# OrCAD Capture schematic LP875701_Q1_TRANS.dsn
size Custom; title: LP875701-Q1 4-Phase 10A Buck Converter with Integrated Switches; rev: 1.0; note: SNVSxxxx –DECEMBER 2018
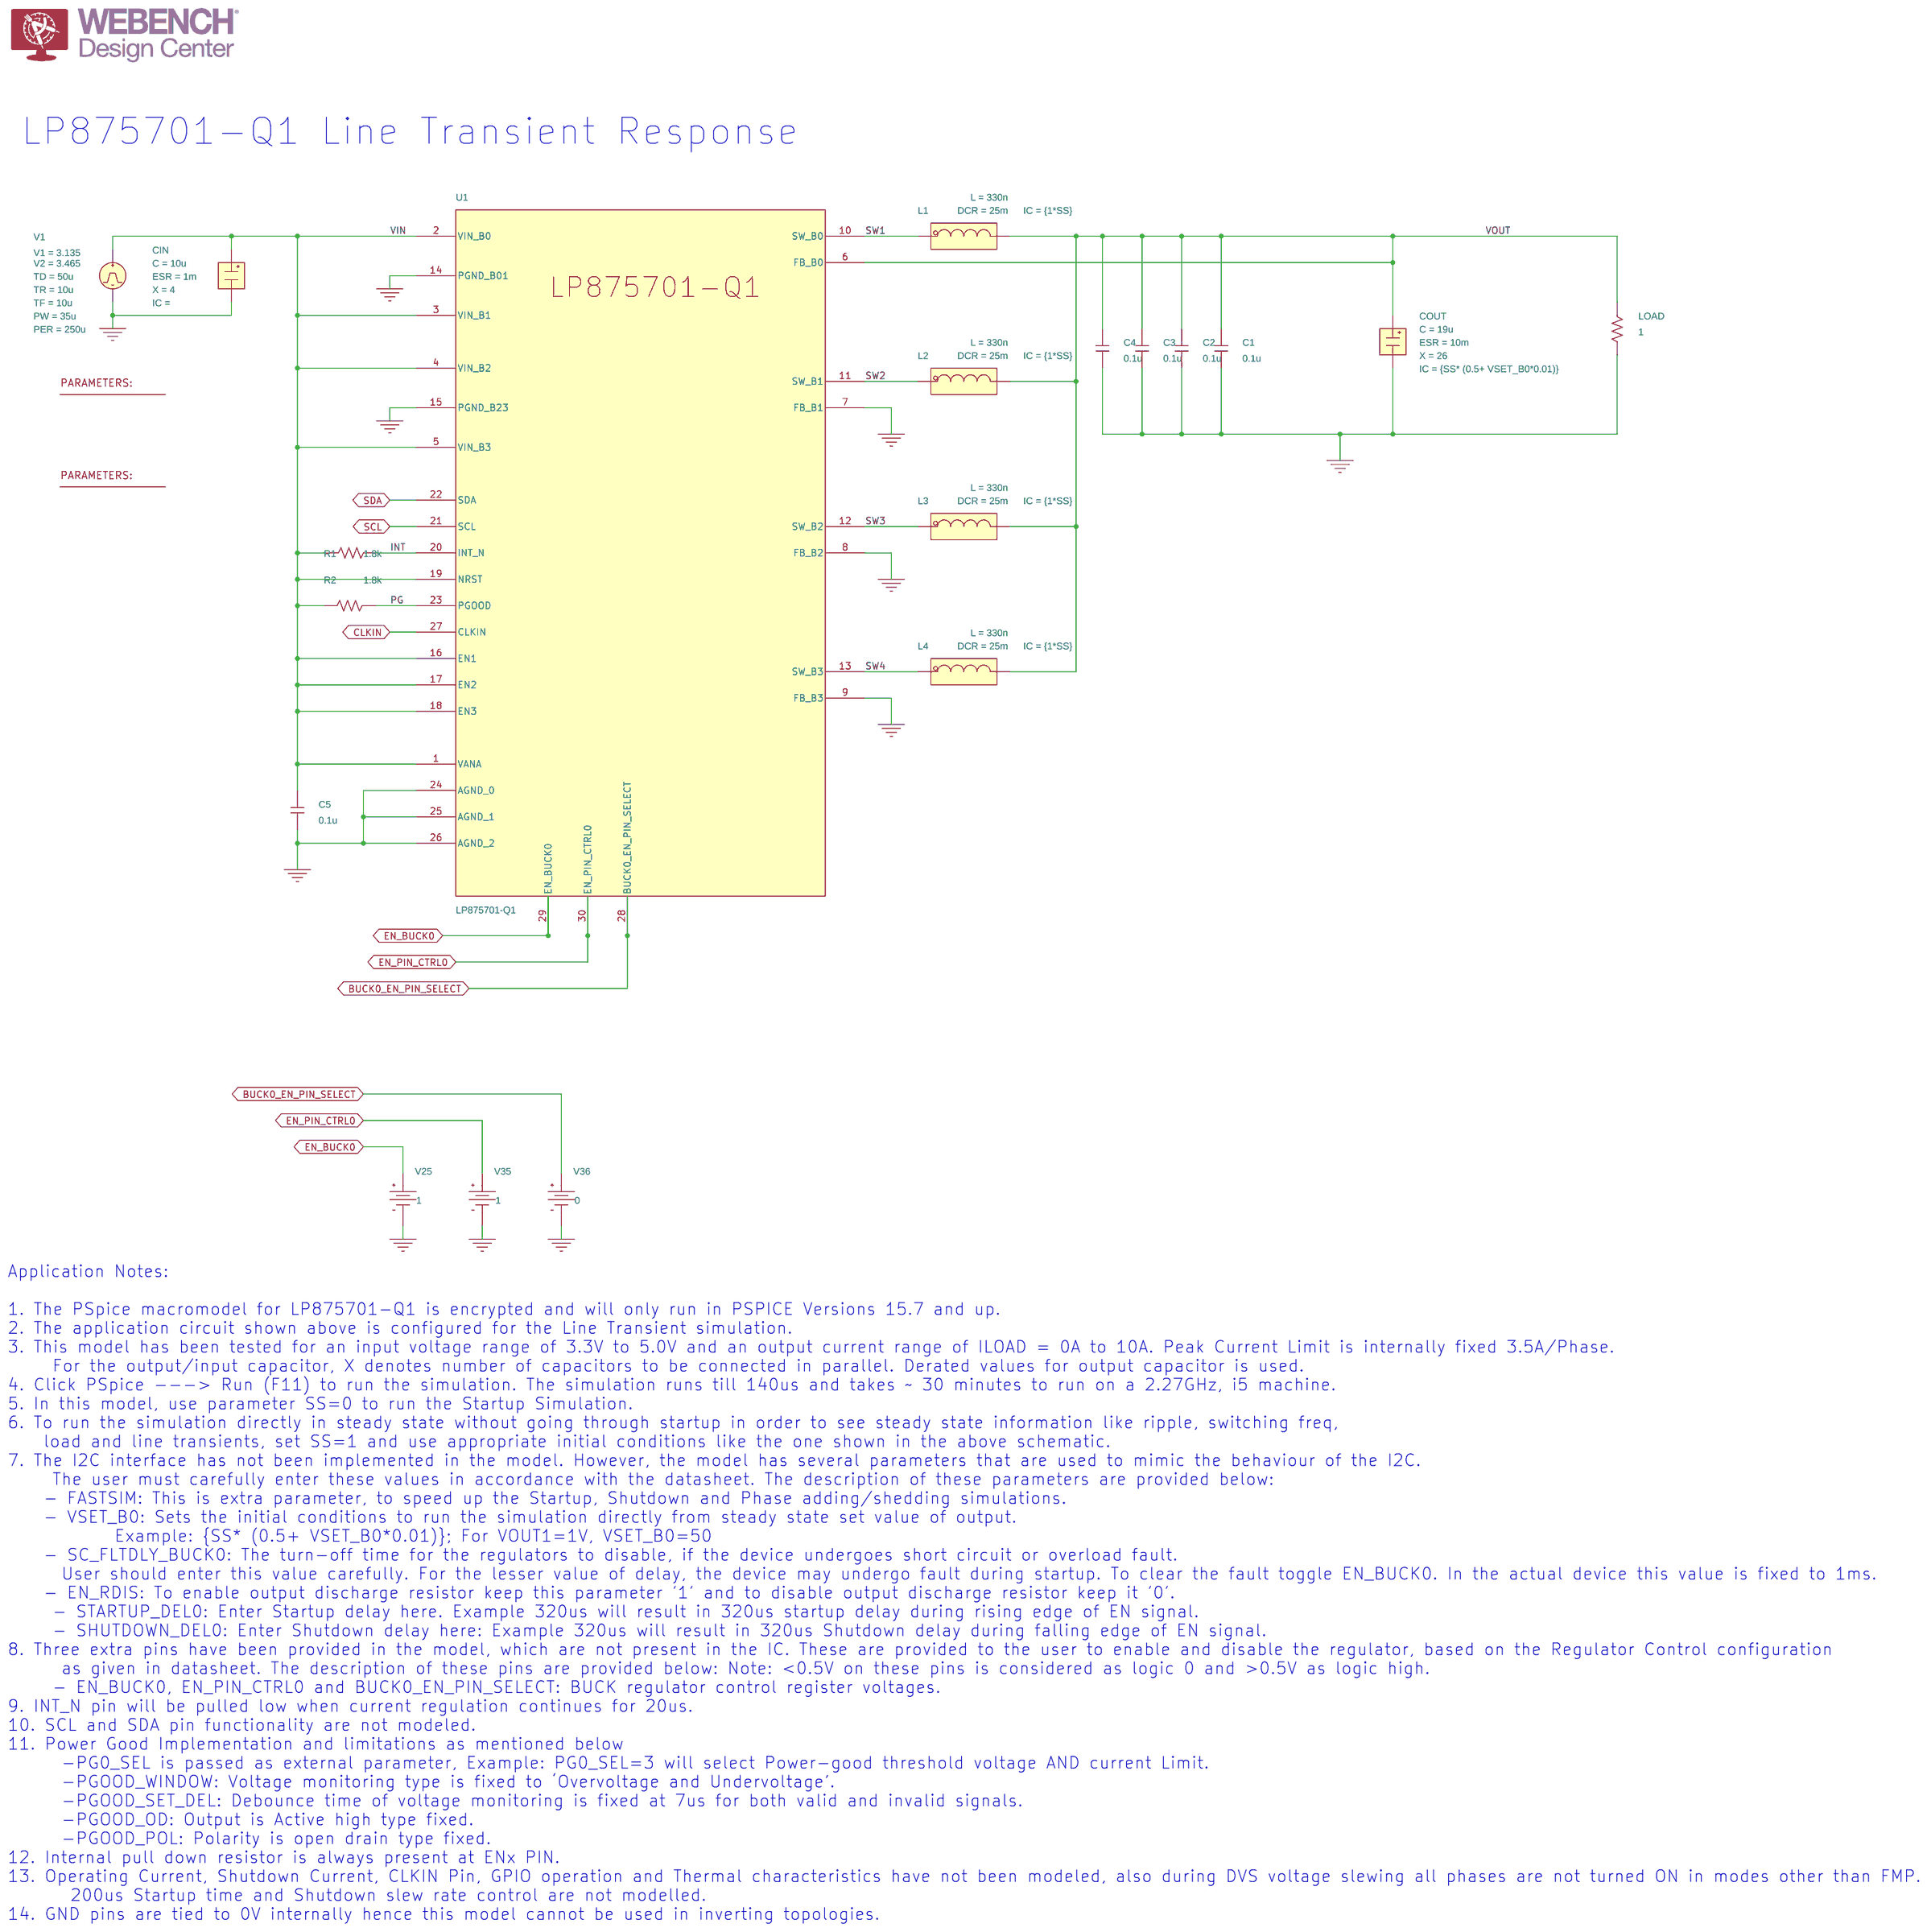
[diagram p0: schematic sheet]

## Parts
5  PARAM
8  PARAM
C1  0.1u  [RAD/CK05]
C2  0.1u  [RAD/CK05]
C3  0.1u  [RAD/CK05]
C4  0.1u  [RAD/CK05]
C5  0.1u  [RAD/CK05]
CIN  CESR
COUT  CESR
L1  LDCR
L2  LDCR
L3  LDCR
L4  LDCR
LOAD  1  [AX/RC05]
R1  1.8k  [AX/RC05]
R2  1.8k  [AX/RC05]
U1  LP875701-Q1
V1  VPULSE
V25  VDC
V35  VDC
V36  VDC

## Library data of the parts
5 = PARAM: EN_RDIS: 1; FASTSIM: 1; PG0_SEL: 3; SC_FLTDLY_BUCK0: 1m; SHUTDOWN_DEL0: 0; STARTUP_DEL0: 0
8 = PARAM: SS: 1; VSET_B0: 50
C1-C5 = C
CIN = CESR: C: 10u; ESR: 1m; PSpiceTemplate: X^@REFDES %IN %OUT @MODEL PARAMS:  ?C|C=@C||C=100u|  ?ESR|ESR=@ESR||ESR=0.01| ?X|X=@X||X=2|  ?IC|IC=@IC||IC=2|; X: 4
COUT = CESR: C: 19u; ESR: 10m; IC: {SS* (0.5+ VSET_B0*0.01)}; PSpiceTemplate: X^@REFDES %IN %OUT @MODEL PARAMS:  ?C|C=@C||C=100u|  ?ESR|ESR=@ESR||ESR=0.01| ?X|X=@X||X=2|  ?IC|IC=@IC||IC=2|; X: 26
L1-L4 = LDCR: DCR: 25m; IC: {1*SS}; L: 330n; PSpiceTemplate: X^@REFDES %IN %OUT @MODEL PARAMS:  ?L|L=@L||L=1u|  ?DCR|DCR=@DCR||DCR=0.01| ?IC|IC=@IC||IC=0|
LOAD R1 R2 = R
U1 = LP875701-Q1_TRANS
V1 = VPULSE: PER: 250u; PW: 35u; TD: 50u; TF: 10u; TR: 10u; V1: 3.135; V2: 3.465
V25 V35 = VDC: DC: 1
V36 = VDC: DC: 0

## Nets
VIN: C5.2 CIN.1(IN) R1.1 R2.2 U1.1(VANA) U1.2(VIN_B0) U1.3(VIN_B1) U1.4(VIN_B2) U1.5(VIN_B3) U1.16(EN1) U1.17(EN2) U1.18(EN3) U1.19(NRST) V1.1(+)
0: C1.1 C2.1 C3.1 C4.1 C5.1 CIN.3(OUT) COUT.3(OUT) LOAD.2 U1.7(FB_B1) U1.8(FB_B2) U1.9(FB_B3) U1.14(PGND_B01) U1.15(PGND_B23) U1.24(AGND_0) U1.25(AGND_1) U1.26(AGND_2) V1.2(-) V25.1(-) V35.1(-) V36.1(-)
BUCK0_EN_PIN_SELECT: U1.28(BUCK0_EN_PIN_SELECT) V36.0(+)
CLKIN: U1.27(CLKIN)
EN_BUCK0: U1.29(EN_BUCK0) V25.0(+)
EN_PIN_CTRL0: U1.30(EN_PIN_CTRL0) V35.0(+)
INT: R1.2 U1.20(INT_N)
PG: R2.1 U1.23(PGOOD)
SCL: U1.21(SCL)
SDA: U1.22(SDA)
SW1: L1.1(IN) U1.10(SW_B0)
SW2: L2.1(IN) U1.11(SW_B1)
SW3: L3.1(IN) U1.12(SW_B2)
SW4: L4.1(IN) U1.13(SW_B3)
VOUT: C1.2 C2.2 C3.2 C4.2 COUT.1(IN) L1.3(OUT) L2.3(OUT) L3.3(OUT) L4.3(OUT) LOAD.1 U1.6(FB_B0)

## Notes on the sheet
- LP875701-Q1 Line Transient Response
- Application Notes:
  1. The PSpice macromodel for LP875701-Q1 is encrypted and will only run in PSPICE Versions 15.7 and up.
  2. The application circuit shown above is configured for the Line Transient simulation.
  3. This model has been tested for an input voltage range of 3.3V to 5.0V and an output current range of ILOAD = 0A to 10A. Peak Current Limit is internally fixed 3.5A/Phase.
       For the output/input capacitor, X denotes number of capacitors to be connected in parallel. Derated values for output capacitor is used.
  4. Click PSpice ---> Run (F11) to run the simulation. The simulation runs till 140us and takes ~ 30 minutes to run on a 2.27GHz, i5 machine.
  5. In this model, use parameter SS=0 to run the Startup Simulation.
  6. To run the simulation directly in steady state without going through startup in order to see steady state information like ripple, switching freq,
      load and line transients, set SS=1 and use appropriate initial conditions like the one shown in the above schematic.
  7. The I2C interface has not been implemented in the model. However, the model has several parameters that are used to mimic the behaviour of the I2C.
       The user must carefully enter these values in accordance with the datasheet. The description of these parameters are provided below:
      - FASTSIM: This is extra parameter, to speed up the Startup, Shutdown and Phase adding/shedding simulations.
      - VSET_B0: Sets the initial conditions to run the simulation directly from steady state set value of output.
  	       Example: {SS* (0.5+ VSET_B0*0.01)}; For VOUT1=1V, VSET_B0=50
      - SC_FLTDLY_BUCK0: The turn-off time for the regulators to disable, if the device undergoes short circuit or overload fault.
        User should enter this value carefully. For the lesser value of delay, the device may undergo fault during startup. To clear the fault toggle EN_BUCK0. In the actual device this value is fixed to 1ms.
      - EN_RDIS: To enable output discharge resistor keep this parameter '1' and to disable output discharge resistor keep it '0'.
       - STARTUP_DEL0: Enter Startup delay here. Example 320us will result in 320us startup delay during rising edge of EN signal.
       - SHUTDOWN_DEL0: Enter Shutdown delay here: Example 320us will result in 320us Shutdown delay during falling edge of EN signal.
  8. Three extra pins have been provided in the model, which are not present in the IC. These are provided to the user to enable and disable the regulator, based on the Regulator Control configuration
        as given in datasheet. The description of these pins are provided below: Note: <0.5V on these pins is considered as logic 0 and >0.5V as logic high.
       - EN_BUCK0, EN_PIN_CTRL0 and BUCK0_EN_PIN_SELECT: BUCK regulator control register voltages.
  9. INT_N pin will be pulled low when current regulation continues for 20us.
  10. SCL and SDA pin functionality are not modeled.
  11. Power Good Implementation and limitations as mentioned below
        -PG0_SEL is passed as external parameter, Example: PG0_SEL=3 will select Power-good threshold voltage AND current Limit.
        -PGOOD_WINDOW: Voltage monitoring type is fixed to ‘Overvoltage and Undervoltage’.
        -PGOOD_SET_DEL: Debounce time of voltage monitoring is fixed at 7us for both valid and invalid signals.
        -PGOOD_OD: Output is Active high type fixed.
        -PGOOD_POL: Polarity is open drain type fixed.
  12. Internal pull down resistor is always present at ENx PIN.
  13. Operating Current, Shutdown Current, CLKIN Pin, GPIO operation and Thermal characteristics have not been modeled, also during DVS voltage slewing all phases are not turned ON in modes other than FMP.
         200us Startup time and Shutdown slew rate control are not modelled.
  14. GND pins are tied to 0V internally hence this model cannot be used in inverting topologies.
